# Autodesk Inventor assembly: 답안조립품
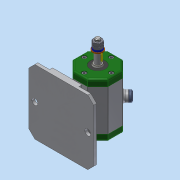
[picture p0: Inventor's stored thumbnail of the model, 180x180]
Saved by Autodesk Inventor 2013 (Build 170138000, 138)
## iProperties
Created: 2018-06
Part Number: 답안조립품
Document SubType Name: Assembly
Designer: Administrator
Author: Administrator
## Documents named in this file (16)
- C:\Users\Administrator\Desktop\480608V1007\답안조립품.iam
- C:\Users\Administrator\Desktop\480608V1007\V벨트풀리.ipt
- C:\Users\Administrator\Desktop\480608V1007\고무캡.ipt
- C:\Users\Administrator\Desktop\480608V1007\너트 M8.ipt
- 너트 M8.ipt
- C:\Users\Administrator\Desktop\480608V1007\뒤커버.ipt
- C:\Users\Administrator\Desktop\480608V1007\베어링 15x32x9.ipt
- C:\Users\Administrator\Desktop\480608V1007\본체.ipt
- C:\Users\Administrator\Desktop\480608V1007\볼트 M4x12.ipt
- C:\Users\Administrator\Desktop\480608V1007\스프링와셔 8.ipt
- C:\Users\Administrator\Desktop\480608V1007\앞커버.ipt
- C:\Users\Administrator\Desktop\480608V1007\오일 실 15 25 7.ipt
- C:\Users\Administrator\Desktop\480608V1007\와셔 8x17.ipt
- C:\Users\Administrator\Desktop\480608V1007\축.ipt
- C:\Users\Administrator\Desktop\480608V1007\키 3x3x12.ipt
- 키 3x3x12.ipt
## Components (2 placed, 2 different names)
1. V벨트풀리:1
2. 고무캡:1
